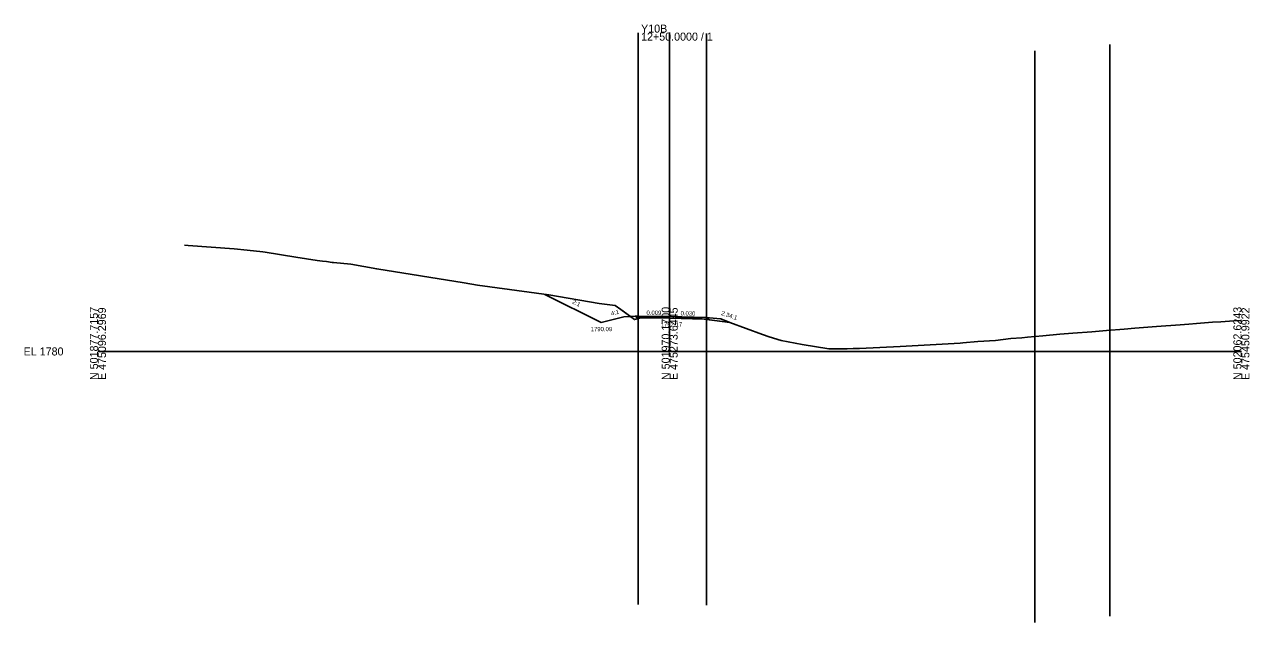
# Model space of a CAD drawing. Extents: x -26 to 1803, y -10 to 9558.
# Drawn here: x -25.7 to 402.8, y 2405.2 to 2614.4 of the extents above; entities that cross this region are included whole.
import ezdxf

# ---------------------------------------------------------------- set-up
doc = ezdxf.new("R2010")
doc.units = 0
for name, color, linetype in [('Exist Cross Section Cell', 7, 'Continuous'), ('Exist XS Center Line Elevation Label', 7, 'Continuous'), ('Exist XS Ground Line', 7, 'Continuous'), ('Prop XS Ditch Slope Text', 7, 'Continuous'), ('Prop XS Ditch Standard Text', 7, 'Continuous'), ('Prop XS Dump Level', 7, 'Continuous'), ('Prop XS Earthwork Shape', 7, 'Continuous'), ('Prop XS EOT Tick Mark', 7, 'Continuous'), ('Prop XS Finish Grade', 7, 'Continuous'), ('Prop XS Finish Grade Earthwork', 7, 'Continuous'), ('Prop XS Finish Grade Pavement', 7, 'Continuous'), ('Prop XS Hydro Typical Ditch Data', 7, 'Continuous'), ('Prop XS Pvmt Edge Slope', 7, 'Continuous'), ('Prop XS SE Text', 7, 'Continuous'), ('Prop XS Shoulder Borrow Shape', 7, 'Continuous'), ('Prop XS Side Slope Text', 7, 'Continuous'), ('Prop XS Subgrade Earthwork', 7, 'Continuous'), ('Scratch_Level_2', 7, 'Continuous')]:
    doc.layers.add(name, color=color, linetype=linetype)

msp = doc.modelspace()

# ---------------------------------------------------------------- linework, layer by layer
at = {"layer": 'Exist Cross Section Cell'}
for p, q in [((200, 2500), (200, 2611.53)), ((0, 2500), (200, 2500)), ((200, 2500), (400, 2500))]:
    msp.add_line(p, q, dxfattribs=at)
at = {"layer": 'Exist XS Ground Line'}
msp.add_lwpolyline([(30.31, 2537.18), (31.6, 2537.04), (47.62, 2535.87), (52.15, 2535.39), (57.65, 2534.85), (58.55, 2534.73), (69.21, 2532.99), (76.73, 2531.85), (78.54, 2531.6), (79.96, 2531.45), (81.9, 2531.17), (82.41, 2531.1), (88.45, 2530.48), (97.51, 2528.89), (128.07, 2523.95), (132.79, 2523.19), (157.7, 2519.75), (175.38, 2516.8), (180.89, 2516.07), (182.97, 2514.66), (187.65, 2511.16), (189.44, 2511.61), (191.65, 2512.13), (197.82, 2512.15), (200.02, 2512.17), (201.92, 2512.1), (209.31, 2511.81), (211.32, 2511.45), (221.04, 2510.1), (232.43, 2505.95), (234.8, 2505.09), (239, 2503.87), (246.39, 2502.39), (255.64, 2500.97), (262.13, 2500.89), (264.16, 2500.98), (266.46, 2501.02), (280.61, 2501.76), (301.6, 2502.88), (302.6, 2503), (307.86, 2503.45), (314.01, 2503.85), (319.4, 2504.49), (323.19, 2504.8), (325.16, 2504.94), (330.6, 2505.44), (336.44, 2506.08), (341.04, 2506.4), (347.72, 2506.85), (352.84, 2507.28), (359, 2507.85), (362.68, 2508.15), (370.28, 2508.7), (378.55, 2509.32), (381.56, 2509.55), (384.31, 2509.76), (389.91, 2510.2), (392.83, 2510.36), (397.33, 2510.7), (400, 2510.79)], dxfattribs=at)
at = {"layer": 'Prop XS Dump Level'}
for p, q in [((189, 2512.34), (200, 2512.24)), ((200, 2512.24), (212.84, 2511.86))]:
    msp.add_line(p, q, dxfattribs=at)
at = {"layer": 'Prop XS Earthwork Shape'}
for points in [[(156.29, 2519.94), (157.7, 2519.75), (175.38, 2516.8), (180.89, 2516.07), (182.97, 2514.66), (186.25, 2512.2), (184, 2512.09), (176, 2510.09)], [(189, 2511.8), (188.46, 2511.81), (187.98, 2512.29), (186.25, 2512.2), (187.65, 2511.16), (189.44, 2511.61), (190.22, 2511.79)], [(197.82, 2512.15), (200.02, 2512.17), (201.92, 2512.1), (209.31, 2511.81), (211.32, 2511.45), (212.11, 2511.34), (200, 2511.7), (190.22, 2511.79), (191.65, 2512.13)], [(212.84, 2511.32), (213.4, 2511.3), (213.87, 2511.78), (217.85, 2511.46), (221.04, 2510.1), (212.11, 2511.34)]]:
    msp.add_lwpolyline(points, close=True, dxfattribs=at)
at = {"layer": 'Prop XS EOT Tick Mark'}
for p, q in [((189, 2512.34), (189, 2513.34)), ((212.84, 2511.86), (212.84, 2512.86))]:
    msp.add_line(p, q, dxfattribs=at)
at = {"layer": 'Prop XS Finish Grade'}
for p, q in [((189, 2512.34), (187.98, 2512.29)), ((212.84, 2511.86), (213.87, 2511.78))]:
    msp.add_line(p, q, dxfattribs=at)
at = {"layer": 'Prop XS Finish Grade Earthwork'}
for p, q in [((176, 2510.09), (156.29, 2519.94)), ((184, 2512.09), (176, 2510.09)), ((187.98, 2512.29), (184, 2512.09)), ((213.87, 2511.78), (217.85, 2511.46)), ((217.85, 2511.46), (221.04, 2510.1))]:
    msp.add_line(p, q, dxfattribs=at)
at = {"layer": 'Prop XS Finish Grade Pavement'}
for p, q in [((189, 2512.34), (200, 2512.24)), ((200, 2512.24), (212.84, 2511.86))]:
    msp.add_line(p, q, dxfattribs=at)
at = {"layer": 'Prop XS Hydro Typical Ditch Data'}
for p, q in [((176, 2510.09), (156.29, 2519.94)), ((184, 2512.09), (176, 2510.09))]:
    msp.add_line(p, q, dxfattribs=at)
at = {"layer": 'Prop XS Pvmt Edge Slope'}
for p, q in [((189, 2512.34), (188.46, 2511.81)), ((212.84, 2511.86), (213.4, 2511.3))]:
    msp.add_line(p, q, dxfattribs=at)
at = {"layer": 'Prop XS Shoulder Borrow Shape'}
for points in [[(189, 2512.34), (187.98, 2512.29), (188.46, 2511.81)], [(212.84, 2511.86), (213.87, 2511.78), (213.4, 2511.3)]]:
    msp.add_lwpolyline(points, close=True, dxfattribs=at)
at = {"layer": 'Prop XS Subgrade Earthwork'}
for p, q in [((188.46, 2511.81), (187.98, 2512.29)), ((189, 2511.8), (188.46, 2511.81)), ((200, 2511.7), (189, 2511.8)), ((212.84, 2511.32), (200, 2511.7)), ((212.84, 2511.32), (213.4, 2511.3)), ((213.4, 2511.3), (213.87, 2511.78))]:
    msp.add_line(p, q, dxfattribs=at)
at = {"layer": 'Scratch_Level_2'}
for p, q in [((189, 2611.5), (189, 2411.5)), ((212.84, 2611.24), (212.84, 2411.24)), ((354, 2607.38), (354, 2407.38)), ((327.8, 2605.19), (327.8, 2405.19))]:
    msp.add_line(p, q, dxfattribs=at)

# ---------------------------------------------------------------- texts
at = {"layer": 'Exist Cross Section Cell'}
for s, p in [('Y10B', (190, 2611.53)), ('12+50.0000 / 1', (190, 2608.73)), ('EL 1780', (-26, 2498.6))]:
    msp.add_text(s, height=2.8, dxfattribs=at).set_placement(p)
for s, p in [('N 501877.7157', (0, 2490)), ('E 475096.2969', (2.8, 2490)), ('N 501970.1700', (200, 2490)), ('E 475273.6445', (202.8, 2490)), ('N 502062.6243', (400, 2490)), ('E 475450.9922', (402.8, 2490))]:
    msp.add_text(s, height=2.8, rotation=90, dxfattribs=at).set_placement(p)
at = {"layer": 'Exist XS Center Line Elevation Label'}
msp.add_text('1792.17', height=1.5, dxfattribs=at).set_placement((196.89, 2508.67))
at = {"layer": 'Prop XS Ditch Slope Text'}
msp.add_text('4:1', height=1.5, rotation=14.0362, dxfattribs=at).set_placement((179.64, 2512.54))
at = {"layer": 'Prop XS Ditch Standard Text'}
msp.add_text('1790.09', height=1.5, dxfattribs=at).set_placement((172.39, 2507.09))
at = {"layer": 'Prop XS Dump Level'}
for p in [(184, 2512.05), (217.85, 2511.42)]:
    msp.add_text('Case1', height=0.04, dxfattribs=at).set_placement(p)
at = {"layer": 'Prop XS SE Text'}
for s, rotation, p in [('0.009', 359.4844, (191.89, 2512.82)), ('0.030', 358.2816, (203.8, 2512.63))]:
    msp.add_text(s, height=1.5, rotation=rotation, dxfattribs=at).set_placement(p)
at = {"layer": 'Prop XS Side Slope Text'}
for s, rotation, p in [('2:1', 333.4349, (165.75, 2516.89)), ('2.34:1', 341.596, (217.9, 2512.8))]:
    msp.add_text(s, height=1.5, rotation=rotation, dxfattribs=at).set_placement(p)

doc.saveas('drawing.dxf')
